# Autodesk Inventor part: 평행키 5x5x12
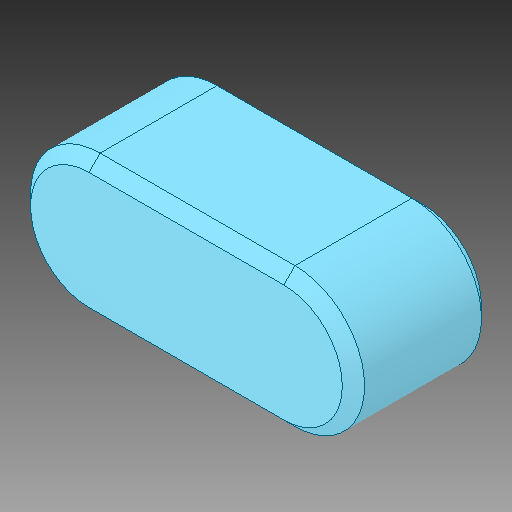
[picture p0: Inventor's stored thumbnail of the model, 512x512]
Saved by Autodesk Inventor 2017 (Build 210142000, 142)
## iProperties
Created: 2024-08
Part Number: 평행키 5x5x12
Material: 일반
Description: 키 및 해당 키홈
Document SubType Name: Modeling
Designer: MRC
Density: 1 g/cm^3
Appearance: 기본값
Author: jhkim
Sending System: Autodesk Inventor 2025
Preprocessor: ST-DEVELOPER v20
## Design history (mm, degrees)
feature "Solid1"
node "솔리드1"
